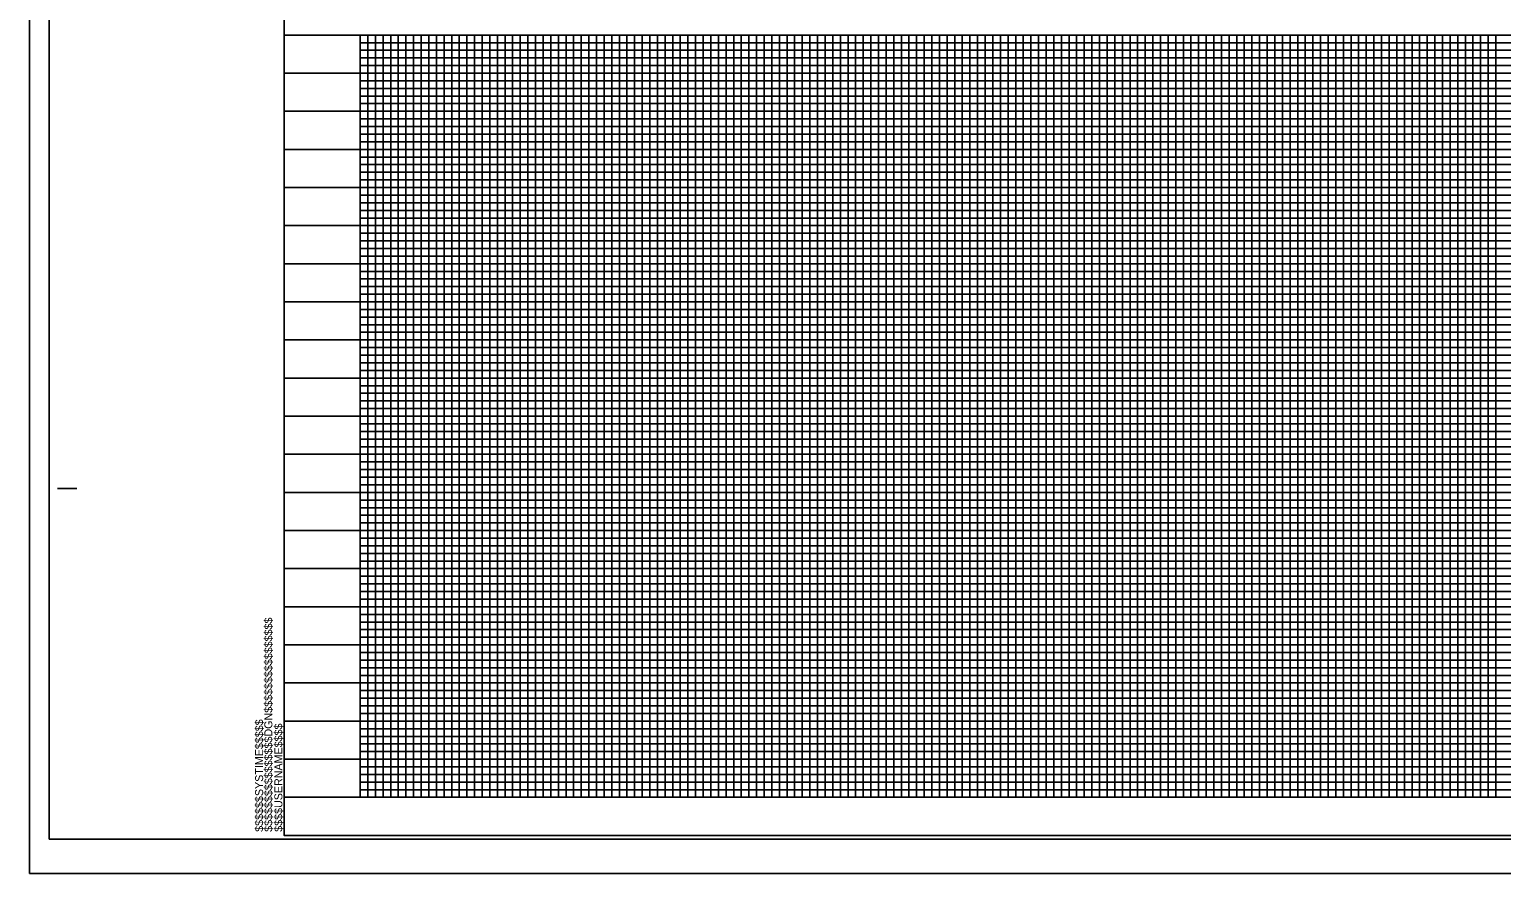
# Model space of a CAD drawing. Extents: x 1648649 to 1651827, y 844691 to 845879.
# Drawn here: x 1649962 to 1650928, y 844691 to 845245 of the extents above; entities that cross this region are included whole.
import ezdxf

# ---------------------------------------------------------------- set-up
doc = ezdxf.new("R2010")
doc.units = 0
for name, color, linetype in [('Sheet Cutting Line CELL', 7, 'Continuous'), ('Sheet DOT Grid CELL', 7, 'Continuous'), ('Sheet Layout Profile Border Port 2', 7, 'Continuous'), ('Sheet Plot Border Inside CELL', 7, 'Continuous'), ('Sheet Plot Border Outside CELL', 7, 'Continuous'), ('Sheet Profile CELL', 7, 'Continuous'), ('Sheet Profile Grid Major CELL', 7, 'Continuous'), ('Sheet Profile Grid Middle CELL', 7, 'Continuous'), ('Sheet Profile Grid Minor CELL', 7, 'Continuous')]:
    doc.layers.add(name, color=color, linetype=linetype)

msp = doc.modelspace()

# ---------------------------------------------------------------- linework, layer by layer
at = {"layer": 'Sheet Cutting Line CELL'}
for p, q in [((1649962.28, 845791.02), (1649962.28, 844691.02)), ((1649962.28, 844691.02), (1651646.28, 844691.02))]:
    msp.add_line(p, q, dxfattribs=at)
at = {"layer": 'Sheet DOT Grid CELL'}
for p, q in [((1650129.28, 845241.02), (1651629.17, 845241.02)), ((1650179.28, 845241.02), (1650179.28, 844741.02)), ((1650229.28, 845241.02), (1650229.28, 844741.02)), ((1650279.28, 845241.02), (1650279.28, 844741.02)), ((1650329.28, 845241.02), (1650329.28, 844741.02)), ((1650379.28, 845241.02), (1650379.28, 844741.02)), ((1650429.28, 845241.02), (1650429.28, 844741.02)), ((1650479.28, 845241.02), (1650479.28, 844741.02)), ((1650529.28, 845241.02), (1650529.28, 844741.02)), ((1650579.28, 845241.02), (1650579.28, 844741.02)), ((1650629.28, 845241.02), (1650629.28, 844741.02)), ((1650679.28, 845241.02), (1650679.28, 844741.02)), ((1650729.28, 845241.02), (1650729.28, 844741.02)), ((1650779.28, 845241.02), (1650779.28, 844741.02)), ((1650829.28, 845241.02), (1650829.28, 844741.02)), ((1650879.28, 845241.02), (1650879.28, 844741.02)), ((1650129.28, 845191.02), (1651629.17, 845191.02)), ((1650129.28, 845141.02), (1651629.17, 845141.02)), ((1650129.28, 845091.02), (1651629.17, 845091.02)), ((1650129.28, 845041.02), (1651629.17, 845041.02)), ((1650129.28, 844991.02), (1651629.17, 844991.02)), ((1650129.28, 844941.02), (1651629.17, 844941.02)), ((1650129.28, 844891.02), (1651629.17, 844891.02)), ((1650129.28, 844841.02), (1651629.17, 844841.02)), ((1650129.28, 844791.02), (1651629.17, 844791.02))]:
    msp.add_line(p, q, dxfattribs=at)
at = {"layer": 'Sheet Layout Profile Border Port 2'}
msp.add_lwpolyline([(1650179.28, 845241.02), (1651579.28, 845241.02), (1651579.28, 844741.02), (1650179.28, 844741.02)], close=True, dxfattribs=at)
at = {"layer": 'Sheet Plot Border Inside CELL'}
msp.add_lwpolyline([(1649975.28, 844713.47), (1651641.78, 844713.47), (1651641.78, 845768.57), (1649975.28, 845768.57)], close=True, dxfattribs=at)
at = {"layer": 'Sheet Plot Border Outside CELL'}
msp.add_lwpolyline([(1649962.28, 844691.02), (1651646.28, 844691.02), (1651646.28, 845791.02), (1649962.28, 845791.02)], close=True, dxfattribs=at)
at = {"layer": 'Sheet Profile CELL'}
for p, q in [((1650129.28, 845241.02), (1651629.28, 845241.02)), ((1649980.78, 844943.52), (1649993.28, 844943.52)), ((1651629.28, 844741.02), (1650129.28, 844741.02)), ((1650129.28, 844716.02), (1651629.28, 844716.02)), ((1650129.28, 844716.02), (1650129.28, 844716.02)), ((1650129.28, 844716.02), (1650129.28, 844716.02)), ((1650129.28, 844716.02), (1650129.28, 844716.02)), ((1650129.28, 844716.02), (1650129.28, 844716.02)), ((1650129.28, 844716.02), (1650129.28, 844716.02)), ((1650129.28, 844716.02), (1650129.28, 844716.02)), ((1650129.28, 844716.02), (1650129.28, 844716.02))]:
    msp.add_line(p, q, dxfattribs=at)
msp.add_lwpolyline([(1651629.28, 845766.02), (1650129.28, 845766.02), (1650129.28, 844716.02), (1651629.28, 844716.02)], close=True, dxfattribs=at)
msp.add_lwpolyline([(1650166.78, 844716.02), (1650166.78, 844716.02)], dxfattribs=at)
at = {"layer": 'Sheet Profile Grid Major CELL'}
for p, q in [((1650629.28, 845241.02), (1650679.28, 845241.02)), ((1650729.28, 845241.02), (1650779.28, 845241.02)), ((1650829.28, 845241.02), (1650879.28, 845241.02)), ((1650129.28, 844741.02), (1650129.28, 844741.02))]:
    msp.add_line(p, q, dxfattribs=at)
for points in [[(1650179.28, 845241.02), (1650179.28, 844741.02), (1650229.28, 844741.02), (1650229.28, 845241.02), (1650279.28, 845241.02), (1650279.28, 844741.02), (1650329.28, 844741.02), (1650329.28, 845241.02), (1650379.28, 845241.02), (1650379.28, 844741.02), (1650429.28, 844741.02), (1650429.28, 845241.02), (1650479.28, 845241.02), (1650479.28, 844741.02), (1650529.28, 844741.02), (1650529.28, 845241.02), (1650579.28, 845241.02), (1650579.28, 844741.02), (1650629.28, 844741.02), (1650629.28, 845241.02), (1650679.28, 845241.02), (1650679.28, 844741.02), (1650729.28, 844741.02), (1650729.28, 845241.02), (1650779.28, 845241.02), (1650779.28, 844741.02), (1650829.28, 844741.02), (1650829.28, 845241.02), (1650879.28, 845241.02), (1650879.28, 844741.02), (1650929.28, 844741.02)], [(1651629.28, 845191.02), (1650129.28, 845191.02)], [(1651629.28, 845141.02), (1650129.28, 845141.02), (1650129.28, 845091.02), (1651629.28, 845091.02)], [(1651629.28, 845041.02), (1650129.28, 845041.02), (1650129.28, 844991.02), (1651629.28, 844991.02)], [(1651629.28, 844941.02), (1650129.28, 844941.02), (1650129.28, 844891.02), (1651629.28, 844891.02)], [(1651629.28, 844841.02), (1650129.28, 844841.02), (1650129.28, 844841.02), (1650129.28, 844791.02), (1651629.28, 844791.02)], [(1651629.28, 844741.02), (1650129.28, 844741.02)]]:
    msp.add_lwpolyline(points, dxfattribs=at)
at = {"layer": 'Sheet Profile Grid Middle CELL'}
for points in [[(1650154.28, 845241.02), (1650204.28, 845241.02), (1650204.28, 844741.02), (1650254.28, 844741.02), (1650254.28, 845241.02), (1650304.28, 845241.02), (1650304.28, 844741.02), (1650354.28, 844741.02), (1650354.28, 845241.02), (1650404.28, 845241.02), (1650404.28, 844741.02), (1650454.28, 844741.02), (1650454.28, 845241.02), (1650504.28, 845241.02), (1650504.28, 844741.02), (1650554.28, 844741.02), (1650554.28, 845241.02), (1650604.28, 845241.02), (1650604.28, 844741.02), (1650654.28, 844741.02), (1650654.28, 845241.02), (1650704.28, 845241.02), (1650704.28, 844741.02), (1650754.28, 844741.02), (1650754.28, 844741.02), (1650754.28, 845241.02), (1650804.28, 845241.02), (1650804.28, 844741.02), (1650854.28, 844741.02), (1650854.28, 845241.02), (1650904.28, 845241.02), (1650904.28, 844741.02), (1650954.28, 844741.02)], [(1650129.28, 845216.02), (1651629.28, 845216.02)], [(1651629.28, 845166.02), (1650129.28, 845166.02), (1650129.28, 845116.02), (1651629.28, 845116.02)], [(1651629.28, 845066.02), (1650129.28, 845066.02), (1650129.28, 845016.02), (1651629.28, 845016.02)], [(1651629.28, 844966.02), (1650129.28, 844966.02), (1650129.28, 844916.02), (1651629.28, 844916.02)], [(1651629.28, 844866.02), (1650129.28, 844866.02), (1650129.28, 844816.02), (1651629.28, 844816.02)], [(1651629.28, 844766.02), (1650129.28, 844766.02)]]:
    msp.add_lwpolyline(points, dxfattribs=at)
at = {"layer": 'Sheet Profile Grid Minor CELL'}
for p, q in [((1650179.28, 845236.02), (1651579.28, 845236.02)), ((1651579.28, 845231.02), (1650179.28, 845231.02)), ((1650179.28, 845226.02), (1651579.28, 845226.02)), ((1651579.28, 845221.02), (1650179.28, 845221.02)), ((1650179.28, 845211.02), (1651579.28, 845211.02)), ((1651579.28, 845206.02), (1650179.28, 845206.02)), ((1650179.28, 845201.02), (1651579.28, 845201.02)), ((1651579.28, 845196.02), (1650179.28, 845196.02)), ((1650179.28, 845186.02), (1651579.28, 845186.02)), ((1651579.28, 845181.02), (1650179.28, 845181.02)), ((1650179.28, 845176.02), (1651579.28, 845176.02)), ((1651579.28, 845171.02), (1650179.28, 845171.02)), ((1650179.28, 845161.02), (1651579.28, 845161.02)), ((1651579.28, 845156.02), (1650179.28, 845156.02)), ((1650179.28, 845151.02), (1651579.28, 845151.02)), ((1651579.28, 845146.02), (1650179.28, 845146.02)), ((1650179.28, 845136.02), (1651579.28, 845136.02)), ((1651579.28, 845131.02), (1650179.28, 845131.02)), ((1650179.28, 845126.02), (1651579.28, 845126.02)), ((1651579.28, 845121.02), (1650179.28, 845121.02)), ((1650179.28, 845111.02), (1651579.28, 845111.02)), ((1651579.28, 845106.02), (1650179.28, 845106.02)), ((1650179.28, 845101.02), (1651579.28, 845101.02)), ((1651579.28, 845096.02), (1650179.28, 845096.02)), ((1650179.28, 845086.02), (1651579.28, 845086.02)), ((1651579.28, 845081.02), (1650179.28, 845081.02)), ((1650179.28, 845076.02), (1651579.28, 845076.02)), ((1651579.28, 845071.02), (1650179.28, 845071.02)), ((1650179.28, 845061.02), (1651579.28, 845061.02)), ((1651579.28, 845056.02), (1650179.28, 845056.02)), ((1650179.28, 845051.02), (1651579.28, 845051.02)), ((1651579.28, 845046.02), (1650179.28, 845046.17)), ((1650179.28, 845036.02), (1651579.28, 845036.02)), ((1651579.28, 845031.02), (1650179.28, 845031.02)), ((1650179.28, 845026.02), (1651579.28, 845026.02)), ((1651579.28, 845021.02), (1650179.28, 845021.02)), ((1650179.28, 845011.02), (1651579.28, 845011.02)), ((1651579.28, 845006.02), (1650179.28, 845006.02)), ((1650179.28, 845001.02), (1651579.28, 845001.02)), ((1651579.28, 844996.02), (1650179.28, 844996.02)), ((1650179.28, 844986.02), (1651579.28, 844986.02)), ((1651579.28, 844981.02), (1650179.28, 844981.02)), ((1650179.28, 844976.02), (1651579.28, 844976.02)), ((1651579.28, 844971.02), (1650179.28, 844971.02)), ((1650179.28, 844961.02), (1651579.28, 844961.02)), ((1651579.28, 844956.02), (1650179.28, 844956.02)), ((1650179.28, 844951.02), (1651579.28, 844951.02)), ((1651579.28, 844946.02), (1650179.28, 844946.02)), ((1650179.28, 844936.02), (1651579.28, 844936.02)), ((1651579.28, 844931.02), (1650179.28, 844931.02)), ((1650179.28, 844926.02), (1651579.28, 844926.02)), ((1651579.28, 844921.02), (1650179.28, 844921.02)), ((1650179.28, 844911.02), (1651579.28, 844911.02)), ((1651579.28, 844906.02), (1650179.28, 844906.02)), ((1650179.28, 844901.02), (1651579.28, 844901.02)), ((1651579.28, 844896.02), (1650179.28, 844896.02)), ((1650179.28, 844886.02), (1651579.28, 844886.02)), ((1651579.28, 844881.02), (1650179.28, 844881.02)), ((1650179.28, 844876.02), (1651579.28, 844876.02)), ((1651579.28, 844871.02), (1650179.28, 844871.02)), ((1650179.28, 844861.02), (1651579.28, 844861.02)), ((1651579.28, 844856.02), (1650179.28, 844856.02)), ((1650179.28, 844851.02), (1651579.28, 844851.02)), ((1651579.28, 844846.02), (1650179.28, 844846.02)), ((1650179.28, 844836.02), (1651579.28, 844836.02)), ((1651579.28, 844831.02), (1650179.28, 844831.02)), ((1650179.28, 844826.02), (1651579.28, 844826.02)), ((1651579.28, 844821.02), (1650179.28, 844821.02)), ((1650179.28, 844811.02), (1651579.28, 844811.02)), ((1651579.28, 844806.02), (1650179.28, 844806.02)), ((1650179.28, 844801.02), (1651579.28, 844801.02)), ((1651579.28, 844796.02), (1650179.28, 844796.02)), ((1650179.28, 844786.02), (1651579.28, 844786.02)), ((1651579.28, 844781.02), (1650179.28, 844781.02)), ((1650179.28, 844776.02), (1651579.28, 844776.02)), ((1651579.28, 844771.02), (1650179.28, 844771.02)), ((1650179.28, 844761.02), (1651579.28, 844761.02)), ((1651579.28, 844756.02), (1650179.28, 844756.02)), ((1650179.28, 844751.02), (1651579.28, 844751.02)), ((1650179.28, 844746.02), (1651579.28, 844746.02))]:
    msp.add_line(p, q, dxfattribs=at)
for points in [[(1650179.28, 845241.02), (1650184.28, 845241.02), (1650184.28, 844741.02), (1650189.28, 844741.02), (1650189.28, 845241.02), (1650194.28, 845241.02), (1650194.28, 844741.02), (1650199.28, 844741.02), (1650199.28, 845241.02), (1650209.28, 845241.02), (1650209.28, 844741.02), (1650214.28, 844741.02), (1650214.28, 845241.02), (1650219.28, 845241.02), (1650219.28, 844741.02), (1650224.28, 844741.02), (1650234.28, 844741.02), (1650239.28, 844741.02), (1650239.28, 845241.02), (1650244.28, 845241.02), (1650244.28, 844741.02), (1650249.28, 844741.02), (1650249.28, 845241.02), (1650259.28, 845241.02), (1650259.28, 844741.02), (1650264.28, 844741.02), (1650264.28, 845241.02), (1650269.28, 845241.02), (1650269.28, 844741.02), (1650274.28, 844741.02), (1650274.28, 845241.02), (1650284.28, 845241.02), (1650284.28, 844741.02), (1650289.28, 844741.02), (1650289.28, 845241.02), (1650294.28, 845241.02), (1650294.28, 844741.02), (1650299.28, 844741.02), (1650299.28, 845241.02), (1650309.28, 845241.02), (1650309.28, 844741.02), (1650314.28, 844741.02), (1650314.28, 845241.02), (1650319.28, 845241.02), (1650319.28, 844741.02), (1650324.28, 844741.02), (1650324.28, 845241.02), (1650334.28, 845241.02), (1650334.28, 844741.02), (1650339.28, 844741.02), (1650339.28, 845241.02), (1650344.28, 845241.02), (1650344.28, 844741.02), (1650349.28, 844741.02), (1650349.28, 845241.02), (1650359.28, 845241.02), (1650359.28, 844741.02), (1650364.28, 844741.02), (1650364.28, 845241.02), (1650369.28, 845241.02), (1650369.28, 844741.02), (1650374.28, 844741.02), (1650374.28, 845241.02), (1650384.28, 845241.02), (1650384.28, 844741.02), (1650389.28, 844741.02), (1650389.28, 845241.02), (1650394.28, 845241.02), (1650394.28, 844741.02)], [(1650224.28, 844741.02), (1650224.28, 845241.02), (1650234.28, 845241.02), (1650234.28, 844741.02)], [(1650394.28, 844741.02), (1650399.28, 844741.02), (1650399.28, 845241.02), (1650409.28, 845241.02), (1650409.28, 844741.02), (1650414.28, 844741.02), (1650414.28, 845241.02), (1650419.28, 845241.02), (1650419.28, 844741.02), (1650424.28, 844741.02), (1650424.28, 845241.02), (1650434.28, 845241.02), (1650434.28, 844741.02), (1650439.28, 844741.02), (1650439.28, 845241.02), (1650444.28, 845241.02), (1650444.28, 844741.02), (1650449.28, 844741.02), (1650449.28, 845241.02), (1650459.28, 845241.02), (1650459.28, 844741.02), (1650464.28, 844741.02), (1650464.28, 845241.02), (1650469.28, 845241.02), (1650469.28, 844741.02), (1650474.28, 844741.02), (1650474.28, 845241.02), (1650484.28, 845241.02), (1650484.28, 844741.02), (1650489.28, 844741.02), (1650489.28, 845241.02), (1650494.28, 845241.02), (1650494.28, 844741.02), (1650499.28, 844741.02), (1650499.28, 845241.02), (1650509.28, 845241.02), (1650509.28, 844741.02), (1650514.28, 844741.02), (1650514.28, 845241.02), (1650519.28, 845241.02), (1650519.28, 844741.02), (1650524.28, 844741.02), (1650524.28, 845241.02), (1650534.28, 845241.02), (1650534.28, 844741.02), (1650539.28, 844741.02), (1650539.28, 845241.02), (1650544.28, 845241.02), (1650544.28, 844741.02), (1650549.28, 844741.02), (1650549.28, 845241.02), (1650559.28, 845241.02), (1650559.28, 844741.02), (1650564.28, 844741.02), (1650564.28, 845241.02), (1650569.28, 845241.02), (1650569.28, 844741.02), (1650574.28, 844741.02), (1650574.28, 845241.02), (1650584.28, 845241.02), (1650584.28, 844741.02), (1650589.28, 844741.02), (1650589.28, 845241.02), (1650594.28, 845241.02), (1650594.28, 844741.02), (1650599.28, 844741.02), (1650599.28, 845241.02), (1650609.28, 845241.02), (1650609.28, 844741.02), (1650614.28, 844741.02), (1650614.28, 845241.02), (1650619.28, 845241.02), (1650619.28, 844741.02), (1650624.28, 844741.02), (1650624.28, 845241.02), (1650634.28, 845241.02), (1650634.28, 844741.02), (1650639.28, 844741.02), (1650639.28, 845241.02), (1650644.28, 845241.02), (1650644.28, 844741.02), (1650649.28, 844741.02), (1650649.28, 845241.02), (1650659.28, 845241.02), (1650659.28, 844741.02), (1650664.28, 844741.02), (1650664.28, 845241.02), (1650669.28, 845241.02), (1650669.28, 844741.02), (1650674.28, 844741.02), (1650674.28, 845241.02), (1650684.28, 845241.02), (1650684.28, 844741.02), (1650689.28, 844741.02), (1650689.28, 845241.02), (1650694.28, 845241.02), (1650694.28, 844741.02), (1650699.28, 844741.02), (1650699.28, 845241.02), (1650709.28, 845241.02)], [(1650709.28, 845241.02), (1650709.28, 844741.02), (1650714.28, 844741.02), (1650714.28, 845241.02), (1650719.28, 845241.02), (1650719.28, 844741.02), (1650724.28, 844741.02), (1650724.28, 845241.02), (1650734.28, 845241.02), (1650734.28, 844741.02), (1650739.28, 844741.02), (1650739.28, 845241.02), (1650744.28, 845241.02), (1650744.28, 844741.02), (1650749.28, 844741.02), (1650749.28, 845241.02), (1650759.28, 845241.02), (1650759.28, 844741.02), (1650764.28, 844741.02), (1650764.28, 845241.02), (1650769.28, 845241.02), (1650769.28, 844741.02), (1650774.28, 844741.02), (1650774.28, 845241.02), (1650784.28, 845241.02), (1650784.28, 844741.02), (1650789.28, 844741.02), (1650789.28, 845241.02), (1650794.28, 845241.02), (1650794.28, 844741.02), (1650799.28, 844741.02), (1650799.28, 845241.02), (1650809.28, 845241.02), (1650809.28, 844741.02), (1650814.28, 844741.02), (1650814.28, 845241.02), (1650819.28, 845241.02), (1650819.28, 844741.02), (1650824.28, 844741.02), (1650824.28, 845241.02), (1650834.28, 845241.02), (1650834.28, 844741.02), (1650834.28, 844741.02), (1650839.28, 844741.02), (1650839.28, 845241.02), (1650844.28, 845241.02), (1650844.28, 844741.02), (1650849.28, 844741.02), (1650849.28, 845241.02), (1650859.28, 845241.02), (1650859.28, 844741.02), (1650864.28, 844741.02), (1650864.28, 845241.02), (1650869.28, 845241.02), (1650869.28, 844741.02), (1650874.28, 844741.02), (1650874.28, 845241.02), (1650884.28, 845241.02), (1650884.28, 844741.02), (1650889.28, 844741.02), (1650889.28, 845241.02), (1650894.28, 845241.02), (1650894.28, 844741.02), (1650899.28, 844741.02), (1650899.28, 845241.02), (1650909.28, 845241.02), (1650909.28, 844741.02), (1650914.28, 844741.02), (1650914.28, 845241.02), (1650919.28, 845241.02), (1650919.28, 844741.02), (1650924.28, 844741.02), (1650924.28, 845241.02), (1650934.28, 845241.02)]]:
    msp.add_lwpolyline(points, dxfattribs=at)

# ---------------------------------------------------------------- texts
at = {"layer": 'Sheet Profile CELL'}
for s, p in [('$$$$$$$$$$$$$$$$DGN$$$$$$$$$$$$$$$$', (1650121.64, 844718.4)), ('$$$$$$SYSTIME$$$$$', (1650115.59, 844718.4)), ('$$$$USERNAME$$$$', (1650128.22, 844718.41))]:
    msp.add_text(s, height=5.25, rotation=90, dxfattribs=at).set_placement(p)

doc.saveas('drawing.dxf')
